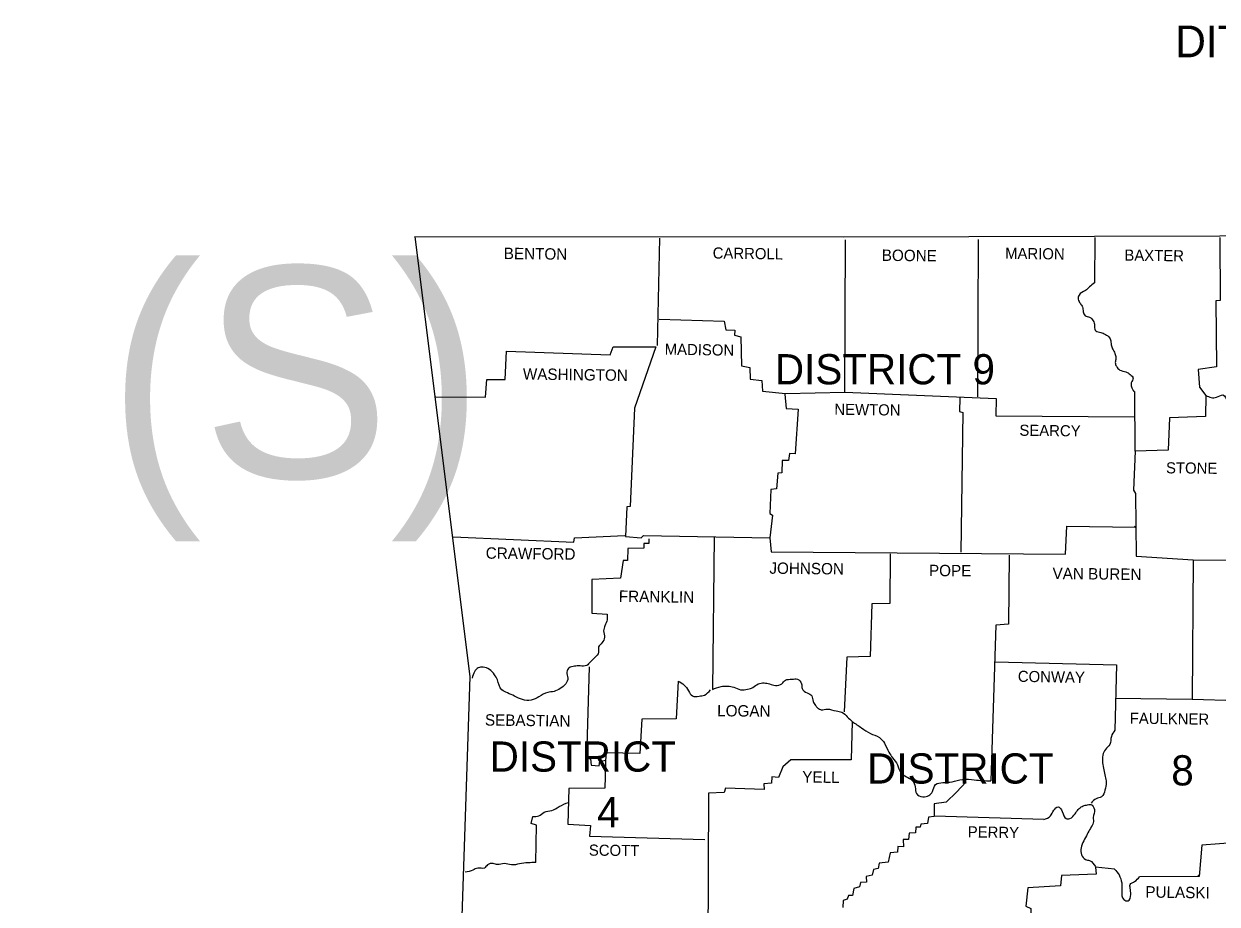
# Model space of a CAD drawing. Extents: x 166 to 3426, y 71 to 2074.
# Drawn here: x 2559.4 to 2999.8, y 1709.8 to 2035 of the extents above; entities that cross this region are included whole.
import ezdxf

# ---------------------------------------------------------------- set-up
doc = ezdxf.new("R2010")
doc.units = 0
for name, color, linetype in [('1', 7, 'Continuous'), ('2', 7, 'Continuous'), ('3', 7, 'Continuous'), ('R_Border', 7, 'Continuous')]:
    doc.layers.add(name, color=color, linetype=linetype)

msp = doc.modelspace()

# ---------------------------------------------------------------- linework, layer by layer
at = {"layer": '1'}
for points in [[(2703.71, 1956.42), (2861.92, 1956.32), (3000.75, 1956.61), (3164.54, 1959.16), (3240.46, 1960.92)], [(2703.71, 1956.42), (2723.96, 1793.81), (2715.15, 1528.37)], [(2794.01, 1955.83), (2793.13, 1916.21)], [(2911.62, 1955.34), (2911.33, 1897.22)], [(2954.67, 1956.03), (2954.47, 1939.3)], [(3000.75, 1956.03), (3000.95, 1932.74), (2999.28, 1932.64), (2999.58, 1908.28), (2992.73, 1907.3), (2993.32, 1900.75), (2995.66, 1897.71), (2995.47, 1889.98), (2982.16, 1889.5), (2981.67, 1877.56), (2969.54, 1877.17), (2968.95, 1862.69), (2969.64, 1861.51), (2969.93, 1838.42), (2990.87, 1837.05), (2990.58, 1785.49), (3007.21, 1785), (3007.21, 1732.56), (2994.1, 1731.58), (2993.12, 1720.04), (2971.11, 1719.94)], [(2793.82, 1925.89), (2817.89, 1925.11), (2818.47, 1921.98), (2821.8, 1921.88), (2821.7, 1919.92), (2824.05, 1919.34), (2824.25, 1908.67), (2827.28, 1907.99), (2827.48, 1903.78), (2831.78, 1903.19), (2831.98, 1899.28), (2840.49, 1898.4), (2862.4, 1898.89), (2862.6, 1955.15)], [(2711.44, 1897.22), (2729.73, 1897.13), (2730.22, 1903.58), (2736.97, 1903.58), (2737.56, 1914.05), (2775.72, 1912.68), (2776.89, 1915.62), (2792.64, 1915.72), (2784.72, 1893.02), (2783.15, 1856.72), (2781.98, 1856.62), (2781.39, 1845.66), (2787.17, 1845.17), (2788.05, 1846.05), (2834.72, 1845.17), (2835.21, 1839.99)], [(2840.29, 1898.2), (2840.68, 1892.92), (2845.18, 1892.63), (2844.01, 1876.19), (2841.96, 1876.29), (2841.56, 1873.65), (2839.22, 1873.65), (2839.12, 1869.14), (2837.65, 1869.05), (2837.16, 1863.27), (2835.01, 1862.98), (2834.72, 1854.17), (2835.69, 1853.49), (2834.72, 1845.17)], [(2862.4, 1898.89), (2918.17, 1896.54), (2918.08, 1890.18), (2969.25, 1889.79)], [(2969.54, 1877.17), (2969.44, 1899.18)], [(2904.77, 1896.83), (2904.67, 1891.75), (2905.94, 1891.45), (2905.16, 1839.79)], [(2717.89, 1845.56), (2762.41, 1843.51), (2762.61, 1845.08), (2781.2, 1845.96)], [(2814.17, 1845.56), (2813.48, 1789.11)], [(2835.21, 1839.99), (2943.81, 1839.11), (2944.3, 1849.38), (2969.54, 1849.09)], [(2969.25, 1849.19), (2969.54, 1849.48)], [(2790, 1844.78), (2790, 1843.02), (2788.14, 1843.02), (2788.24, 1841.26), (2782.27, 1841.16), (2782.18, 1836.76), (2780.51, 1836.76), (2779.63, 1830.2), (2769.06, 1829.71), (2768.97, 1817.29), (2774.64, 1816.9)], [(2879.14, 1839.21), (2879.04, 1820.91), (2872.29, 1820.81), (2871.7, 1801.34), (2863.09, 1801.05), (2862.11, 1780.89)], [(2922.97, 1838.72), (2922.77, 1813.28), (2918.08, 1812.89), (2916.22, 1755.36)], [(2990.87, 1837.05), (3041.16, 1836.76), (3045.46, 1838.81), (3045.17, 1800.56), (3042.24, 1799.29), (3039.59, 1797.04), (3038.71, 1796.16), (3038.62, 1785.2), (3006.62, 1785.2)], [(2767.99, 1797.53), (2767.01, 1763.87), (2768.48, 1763.48), (2768.77, 1761.13), (2771.71, 1760.93), (2772, 1762.6), (2774.35, 1762.99)], [(2917.88, 1799.29), (2962.59, 1798.21), (2962.01, 1774.04)], [(2800.86, 1792.24), (2800.18, 1778.25), (2787.46, 1778.15), (2786.77, 1765.43), (2774.15, 1765.73), (2773.76, 1752.62), (2760.55, 1752.52), (2760.16, 1739.41), (2768.48, 1738.92), (2768.18, 1734.91), (2810.65, 1733.73)], [(2962.1, 1785.88), (2990.58, 1785.49)], [(2865.14, 1777.27), (2864.75, 1763.18), (2842.45, 1763.09), (2839.51, 1760.54), (2837.85, 1756.63), (2835.4, 1756.82), (2835.3, 1754.57), (2832.47, 1754.28), (2832.56, 1752.22), (2818.38, 1752.62), (2817.89, 1751.05), (2812.02, 1750.86), (2811.82, 1693.62)], [(2907.12, 1754.96), (2903.6, 1751.15), (2899.78, 1747.53), (2895.38, 1746.84), (2895.38, 1742.25), (2893.22, 1741.95), (2892.83, 1739.6), (2890.39, 1739.41), (2890.19, 1738.33), (2888.53, 1738.23), (2888.43, 1736.18), (2886.08, 1736.08), (2885.89, 1733.73), (2883.93, 1733.73), (2884.03, 1730.99), (2881.88, 1731.19), (2881.78, 1729.04), (2879.14, 1728.84), (2878.35, 1725.32), (2875.03, 1725.03), (2874.73, 1723.07), (2872.97, 1722.58), (2872.48, 1720.52), (2870.23, 1720.04), (2870.43, 1717.98), (2868.18, 1717.78), (2867.79, 1716.22), (2865.73, 1715.63), (2865.24, 1712.99), (2863.68, 1713.09), (2863.19, 1711.72), (2861.72, 1711.23), (2861.62, 1708.59)], [(2748.32, 1725.22), (2748.62, 1739.02), (2746.66, 1739.6), (2747.25, 1742.25)], [(2935.79, 1741.07), (2895.47, 1742.34)], [(2961.91, 1722.77), (2954.86, 1723.56), (2955.16, 1720.92), (2942.34, 1720.43), (2941.95, 1716.61), (2929.91, 1715.93), (2929.23, 1709.08), (2930.99, 1708.2), (2930.99, 1703.7)], [(2992.63, 1720.13), (2993.12, 1720.62)]]:
    msp.add_lwpolyline(points, dxfattribs=at)
for points in [[(2954.47, 1939.3), (2952.71, 1937.83), (2951.15, 1936.46), (2948.8, 1934.8), (2948.5, 1933.23), (2949.29, 1931.66), (2950.07, 1930.39), (2950.36, 1928.63), (2951.05, 1927.16), (2952.71, 1926.58), (2954.08, 1925.31), (2954.57, 1923.54), (2954.77, 1921.88), (2956.33, 1921.1), (2958.09, 1920.51), (2959.76, 1919.34), (2960.54, 1917.87), (2960.73, 1916.01), (2961.42, 1914.54), (2962.2, 1912.78), (2962.4, 1911.31), (2962.2, 1909.85), (2962.59, 1908.48), (2963.87, 1907.11), (2966.12, 1906.42), (2967.68, 1905.44), (2968.76, 1904.07), (2968.07, 1902.41), (2968.17, 1900.94), (2969.05, 1899.18)], [(2995.66, 1897.71), (2999.58, 1897.03), (3001.93, 1897.91), (3003.59, 1895.37), (3004.47, 1893.41), (3005.94, 1890.57), (3008.29, 1889.69), (3010.05, 1888.13), (3010.05, 1886.46), (3008.48, 1884.9), (3007.31, 1883.33), (3007.7, 1881.47), (3008.09, 1878.93), (3008.09, 1876.48), (3007.5, 1874.23), (3007.01, 1872.18), (3007.5, 1870.42), (3009.36, 1870.71), (3011.32, 1872.18), (3013.37, 1872.18), (3015.33, 1871.1), (3017.38, 1869.24), (3019.44, 1869.63), (3021.1, 1870.12), (3023.45, 1870.81), (3025.11, 1869.93), (3026.58, 1868.75), (3028.34, 1866.89), (3030.01, 1865.72), (3032.16, 1864.64), (3034.8, 1863.96), (3037.25, 1862.3), (3037.64, 1859.46), (3037.54, 1857.01), (3037.34, 1853.98), (3037.15, 1850.65), (3037.44, 1847.42), (3038.52, 1845.27), (3039.89, 1842.73), (3040.28, 1840.38), (3040.18, 1836.66)], [(2774.64, 1816.9), (2774.64, 1814.84), (2773.86, 1812.69), (2773.37, 1810.83), (2773.66, 1808.39), (2772.78, 1806.43), (2771.51, 1804.86), (2771.51, 1802.91), (2770.04, 1800.85), (2768.48, 1799.29), (2767.11, 1798.01), (2764.66, 1797.82), (2762.61, 1797.72), (2760.55, 1797.04), (2759.77, 1795.57), (2760.16, 1793.32), (2759.38, 1791.17), (2757.32, 1789.5), (2755.07, 1788.43), (2752.73, 1788.03), (2749.5, 1786.47), (2746.56, 1785.2), (2743.43, 1785.39), (2740.5, 1786.66), (2737.85, 1787.84), (2735.8, 1789.01), (2734.14, 1792.63), (2733.06, 1794.59), (2731.2, 1796.55), (2728.95, 1797.33), (2727.09, 1797.13), (2724.84, 1793.32)], [(2813.48, 1789.11), (2816.71, 1790.19), (2819.06, 1790.38), (2821.41, 1789.99), (2823.86, 1789.01), (2826.5, 1789.21), (2828.45, 1789.89), (2830.41, 1791.17), (2832.56, 1791.56), (2834.62, 1791.17), (2836.77, 1790.58), (2839.12, 1791.26), (2840.49, 1792.54), (2842.84, 1792.93), (2844.89, 1792.93), (2846.36, 1791.26), (2846.65, 1789.5), (2848.51, 1787.84), (2850.17, 1786.76), (2850.66, 1784.71), (2851.54, 1783.24), (2852.43, 1782.26), (2853.7, 1781.67), (2855.85, 1781.87), (2859.18, 1781.19), (2861.33, 1780.7), (2863.29, 1779.03), (2865.14, 1777.27)], [(2800.86, 1792.24), (2803.02, 1790.87), (2804.68, 1788.62), (2806.15, 1786.76), (2808.59, 1786.66), (2810.55, 1787.06), (2812.8, 1789.01)], [(2865.14, 1777.27), (2868.57, 1774.92), (2871.8, 1772.87), (2875.12, 1771.4), (2876.98, 1769.25), (2878.65, 1765.92), (2880.02, 1763.87), (2881.78, 1761.32), (2883.05, 1758.49), (2885.1, 1756.92), (2887.26, 1755.55), (2888.33, 1753.11), (2888.82, 1750.66), (2891.17, 1749.49), (2893.42, 1749.97), (2894.69, 1751.44), (2895.87, 1753.99), (2898.51, 1754.77), (2901.93, 1755.06), (2905.85, 1755.94), (2910.15, 1755.75), (2916.22, 1755.36)], [(2962.01, 1774.04), (2960.73, 1771.79), (2960.15, 1768.86), (2958.58, 1767), (2957.6, 1764.85), (2957.51, 1762.01), (2958, 1759.47), (2958.48, 1757.02), (2958.88, 1754.77), (2958.39, 1751.93), (2957.11, 1749.49), (2955.16, 1748.8), (2953.3, 1747.14)], [(2747.25, 1742.25), (2749.4, 1742.44), (2751.45, 1743.81), (2754.19, 1744.4), (2756.93, 1745.87), (2760.36, 1747.43)], [(2935.79, 1741.07), (2938.23, 1742.44), (2939.5, 1744.5), (2941.07, 1745.77), (2942.63, 1744.01), (2944, 1741.46), (2945.47, 1741.46), (2947.33, 1743.22), (2948.5, 1744.79), (2949.97, 1745.96), (2951.54, 1746.45), (2953.2, 1746.65), (2954.47, 1744.79), (2954.08, 1741.85), (2954.08, 1739.9), (2953.01, 1737.84), (2951.83, 1735.69), (2950.56, 1733.24), (2949.58, 1730.6), (2949.78, 1728.06), (2951.15, 1726.39), (2952.71, 1725.91), (2954.86, 1723.75)], [(2748.32, 1725.22), (2745.49, 1725.12), (2742.26, 1724.73), (2739.32, 1724.34), (2736.68, 1724.83), (2734.23, 1724.44), (2732.57, 1724.83), (2730.52, 1724.34), (2729.34, 1723.17), (2726.9, 1723.17), (2725.13, 1722.38), (2722.3, 1721.7)], [(2961.91, 1722.77), (2963.57, 1720.62), (2964.55, 1717.69), (2964.55, 1714.36), (2965.33, 1711.62), (2966.9, 1711.03), (2967.88, 1713.38), (2967.68, 1715.73), (2967.68, 1717.1), (2969.34, 1718.27), (2971.11, 1719.94)]]:
    msp.add_spline(points, degree=3, dxfattribs=at)

# ---------------------------------------------------------------- texts
at = {"layer": '2'}
for s, height, rotation, p in [('BENTON', 4.207, 359.2527, (2736.48, 1948.1)), ('CARROLL', 4.109, 359.1481, (2813.58, 1948.3)), ('BOONE', 4.207, 359.4001, (2876, 1947.42)), ('MARION', 4.109, 359.1854, (2921.5, 1948.2)), ('BAXTER', 4.109, 359.2559, (2965.53, 1947.51)), ('MADISON', 4.109, 359.0906, (2795.87, 1912.78)), ('WASHINGTON', 4.206, 359.232, (2743.53, 1903.58)), ('NEWTON', 4.109, 359.2717, (2858.49, 1890.57)), ('SEARCY', 4.108, 359.2527, (2926.78, 1882.84)), ('STONE', 4.108, 359.4001, (2980.89, 1868.95)), ('CRAWFORD', 4.206, 359.2771, (2729.83, 1837.44)), ('JOHNSON', 4.207, 359.3514, (2834.52, 1831.87)), ('POPE', 4.207, 359.6155, (2893.42, 1830.99)), ('VAN BUREN', 4.207, 359.3508, (2939.01, 1829.91)), ('FRANKLIN', 4.207, 359.1815, (2778.95, 1821.5)), ('CONWAY', 4.108, 359.0371, (2926.2, 1791.95)), ('SEBASTIAN', 4.206, 359.2816, (2729.54, 1775.8)), ('LOGAN', 4.207, 359.3969, (2815.25, 1779.23)), ('FAULKNER', 4.109, 359.2486, (2967.49, 1776.49)), ('YELL', 4.207, 359.1987, (2846.65, 1754.77)), ('PERRY', 4.109, 359.0858, (2907.71, 1734.52)), ('SCOTT', 4.109, 359.4063, (2767.89, 1727.76)), ('PULASKI', 4.207, 359.053, (2973.26, 1712.31))]:
    msp.add_text(s, height=height, rotation=rotation, dxfattribs=at).set_placement(p)
msp.add_text('DITCH NO. 35 STR.  & APPRS. (S)', height=78, dxfattribs=at).set_placement((1077.58, 1867.33))
at = {"layer": '3'}
for s, height, p in [('DISTRICT 9', 11.154, (2836.57, 1901.82)), ('DISTRICT', 11.154, (2731.3, 1758.78)), ('DISTRICT', 11.154, (2870.62, 1754.38)), ('8', 11.15, (2982.85, 1753.69)), ('4', 11.15, (2770.92, 1738.23))]:
    msp.add_text(s, height=height, dxfattribs=at).set_placement(p)
at = {"layer": 'R_Border'}
msp.add_text('DITCH NO. 35 STR. & APPRS. (S)', height=11.724, dxfattribs=at).set_placement((2984.31, 2022.61))

doc.saveas('drawing.dxf')
